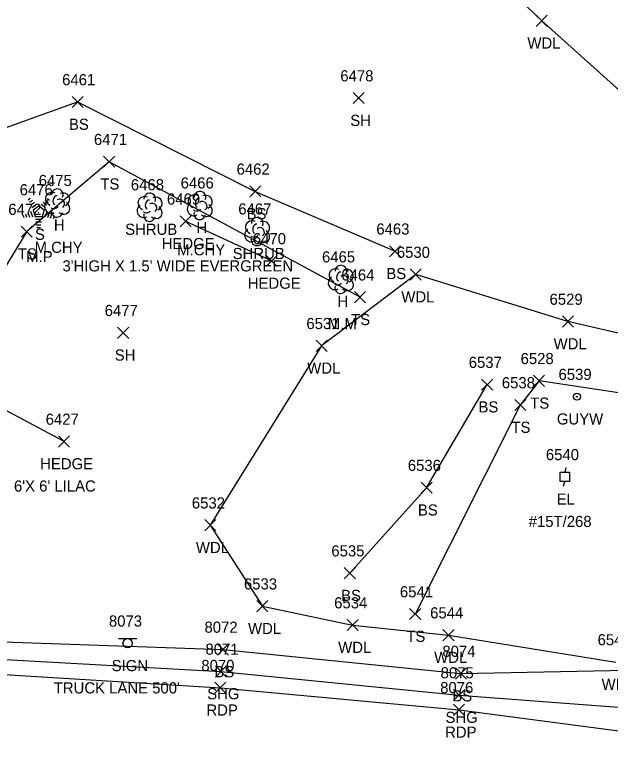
# Model space of a CAD drawing. Extents: x 1588028 to 1589597, y 137576 to 138176.
# Drawn here: x 1588667.4 to 1588774.4, y 137897.5 to 138029.2 of the extents above; entities that cross this region are included whole.
import ezdxf

# ---------------------------------------------------------------- set-up
doc = ezdxf.new("R2010")
doc.units = 0
for name, color, linetype in [('L_A', 7, 'Continuous'), ('L_C', 7, 'Continuous'), ('L_I', 7, 'Continuous'), ('L_TIC', 7, 'Continuous'), ('LAHR', 7, 'Continuous'), ('LAWA', 7, 'Continuous'), ('LELB', 7, 'Continuous'), ('LSH', 7, 'Continuous'), ('LTC', 7, 'Continuous'), ('LTD', 7, 'Continuous'), ('P_A', 7, 'Continuous'), ('P_I', 7, 'Continuous'), ('P_TIC', 7, 'Continuous'), ('PET', 7, 'Continuous'), ('PSU', 7, 'Continuous'), ('S_A', 7, 'Continuous'), ('S_C', 7, 'Continuous'), ('S_I', 7, 'Continuous'), ('SSGN', 7, 'Continuous'), ('U_A', 7, 'Continuous'), ('U_C', 7, 'Continuous'), ('U_I', 7, 'Continuous'), ('UEPT', 7, 'Continuous'), ('UPGW', 7, 'Continuous')]:
    doc.layers.add(name, color=color, linetype=linetype)

msp = doc.modelspace()

# ---------------------------------------------------------------- linework, layer by layer
at = {"layer": 'L_TIC'}
for points in [[(1588761.05, 138027.09), (1588763.05, 138029.09)], [(1588763.05, 138027.09), (1588761.05, 138029.09)], [(1588728.17, 138013.21), (1588730.17, 138015.21)], [(1588730.17, 138013.21), (1588728.17, 138015.21)], [(1588677.67, 138012.51), (1588679.67, 138014.51)], [(1588679.67, 138012.51), (1588677.67, 138014.51)], [(1588683.34, 138001.79), (1588685.34, 138003.79)], [(1588685.34, 138001.79), (1588683.34, 138003.79)], [(1588709.59, 137996.46), (1588711.59, 137998.46)], [(1588711.59, 137996.46), (1588709.59, 137998.46)], [(1588697.07, 137991.09), (1588699.07, 137993.09)], [(1588699.07, 137991.09), (1588697.07, 137993.09)], [(1588668.52, 137989.24), (1588670.52, 137991.24)], [(1588670.52, 137989.24), (1588668.52, 137991.24)], [(1588734.69, 137985.71), (1588736.69, 137987.71)], [(1588736.69, 137985.71), (1588734.69, 137987.71)], [(1588712.54, 137983.98), (1588714.54, 137985.98)], [(1588714.54, 137983.98), (1588712.54, 137985.98)], [(1588738.41, 137981.53), (1588740.41, 137983.53)], [(1588740.41, 137981.53), (1588738.41, 137983.53)], [(1588728.4, 137977.46), (1588730.4, 137979.46)], [(1588730.4, 137977.46), (1588728.4, 137979.46)], [(1588765.76, 137973.1), (1588767.76, 137975.1)], [(1588767.76, 137973.1), (1588765.76, 137975.1)], [(1588685.84, 137971.08), (1588687.84, 137973.08)], [(1588687.84, 137971.08), (1588685.84, 137973.08)], [(1588721.5, 137968.74), (1588723.5, 137970.74)], [(1588723.5, 137968.74), (1588721.5, 137970.74)], [(1588751.24, 137961.77), (1588753.24, 137963.77)], [(1588753.24, 137961.77), (1588751.24, 137963.77)], [(1588760.56, 137962.45), (1588762.56, 137964.45)], [(1588762.56, 137962.45), (1588760.56, 137964.45)], [(1588757.19, 137958.11), (1588759.19, 137960.11)], [(1588759.19, 137958.11), (1588757.19, 137960.11)], [(1588675.23, 137951.57), (1588677.23, 137953.57)], [(1588677.23, 137951.57), (1588675.23, 137953.57)], [(1588740.36, 137943.27), (1588742.36, 137945.27)], [(1588742.36, 137943.27), (1588740.36, 137945.27)], [(1588701.5, 137936.53), (1588703.5, 137938.53)], [(1588703.5, 137936.53), (1588701.5, 137938.53)], [(1588726.56, 137927.93), (1588728.56, 137929.93)], [(1588728.56, 137927.93), (1588726.56, 137929.93)], [(1588710.86, 137921.99), (1588712.86, 137923.99)], [(1588712.86, 137921.99), (1588710.86, 137923.99)], [(1588738.31, 137920.58), (1588740.31, 137922.58)], [(1588740.31, 137920.58), (1588738.31, 137922.58)], [(1588727.07, 137918.6), (1588729.07, 137920.6)], [(1588729.07, 137918.6), (1588727.07, 137920.6)], [(1588744.3, 137916.8), (1588746.3, 137918.8)], [(1588746.3, 137916.8), (1588744.3, 137918.8)], [(1588703.8, 137914.23), (1588705.8, 137916.23)], [(1588705.8, 137914.23), (1588703.8, 137916.23)], [(1588746.54, 137909.9), (1588748.54, 137911.9)], [(1588748.54, 137909.9), (1588746.54, 137911.9)]]:
    msp.add_lwpolyline(points, dxfattribs=at)
at = {"layer": 'LAHR'}
for points in [[(1588698.07, 137992.09), (1588713.54, 137984.98)], [(1588676.23, 137952.57), (1588652.59, 137965.15)]]:
    msp.add_lwpolyline(points, dxfattribs=at)
at = {"layer": 'LAWA'}
for points in [[(1588438.89, 138034.8), (1588460.15, 138038.23), (1588480.55, 138035.11), (1588505.29, 138026.54), (1588523.98, 138028.49), (1588536.66, 138053.55), (1588553.84, 138097.83), (1588585.17, 138100.47), (1588614.56, 138103.49), (1588645.11, 138105.26), (1588662.06, 138103.96), (1588684.62, 138095.19), (1588717.93, 138069.71), (1588741.65, 138047.62), (1588762.05, 138028.09), (1588788.28, 138004.54)], [(1588793.35, 137967.95), (1588766.76, 137974.1), (1588739.41, 137982.53), (1588722.5, 137969.74), (1588702.5, 137937.53), (1588711.86, 137922.99), (1588728.07, 137919.6), (1588745.3, 137917.8), (1588775.38, 137912.97)]]:
    msp.add_lwpolyline(points, dxfattribs=at)
at = {"layer": 'LELB'}
for points in [[(1588591.54, 138046.29), (1588626.32, 138039.75), (1588630.34, 138007.04), (1588626.86, 137991.11), (1588639.77, 137986.11), (1588660.41, 138007.02), (1588678.67, 138013.51), (1588710.59, 137997.46), (1588735.69, 137986.71)], [(1588729.4, 137978.46), (1588684.34, 138002.79), (1588669.52, 137990.24), (1588656.54, 137969.04)], [(1588806.13, 137923.03), (1588809.17, 137939.49), (1588786.18, 137959.73), (1588761.56, 137963.45), (1588758.19, 137959.11), (1588739.31, 137921.58)], [(1588727.56, 137928.93), (1588741.36, 137944.27), (1588752.24, 137962.77)], [(1588551.14, 137930.49), (1588555.16, 137922.7), (1588594.96, 137920.46), (1588624.61, 137918.77), (1588663.54, 137916.63), (1588704.8, 137915.23), (1588747.54, 137910.9), (1588783.34, 137911.62)]]:
    msp.add_lwpolyline(points, dxfattribs=at)
at = {"layer": 'LSH'}
for p, q in [((1588691.58, 137994.66), (1588691.58, 137994.66)), ((1588691.58, 137994.66), (1588691.58, 137994.66)), ((1588710.89, 137990.31), (1588710.89, 137990.31)), ((1588710.89, 137990.31), (1588710.89, 137990.31))]:
    msp.add_line(p, q, dxfattribs=at)
for centre in [(1588691.63, 137996.09), (1588710.93, 137991.74)]:
    msp.add_arc(centre, 1.05, 335.5272, 180.9563, dxfattribs=at)
for centre, major_axis, ratio, start_param, end_param in [((1588690.79, 137995.32), (1.21, -0.51), 0.895232, 1.570796, 4.712389), ((1588692.62, 137995.24), (-1.14, -0.48), 0.949671, 1.570796, 4.712389), ((1588690.5, 137993.95), (0.58, -1.04), 0.959034, 3.141593, 6.283185), ((1588691.37, 137995.11), (-0.208, -0.792), 0.645439, 3.141593, 6.283185), ((1588692.08, 137994.49), (-0.5, 0.667), 0.989748, 3.141593, 6.283185), ((1588691.12, 137993.91), (-0.625, -0.083), 0.423636, 0, 3.141593), ((1588692.58, 137993.82), (-1.09, 0.79), 0.841452, 1.570796, 4.712389), ((1588691.58, 137993.16), (0.26, 1.06), 0.942809, 1.570796, 4.712389), ((1588710.1, 137990.98), (1.21, -0.51), 0.895232, 1.570796, 4.712389), ((1588711.93, 137990.89), (-1.14, -0.48), 0.949671, 1.570796, 4.712389), ((1588710.68, 137990.77), (-0.208, -0.792), 0.645439, 3.141593, 6.283185), ((1588711.39, 137990.14), (-0.5, 0.667), 0.989748, 3.141593, 6.283185), ((1588709.8, 137989.6), (0.58, -1.04), 0.959034, 3.141593, 6.283185), ((1588710.43, 137989.56), (-0.625, -0.083), 0.423636, 0, 3.141593), ((1588711.89, 137989.48), (-1.09, 0.79), 0.841452, 1.570796, 4.712389), ((1588710.89, 137988.81), (0.26, 1.06), 0.942809, 1.570796, 4.712389)]:
    msp.add_ellipse(centre, major_axis=major_axis, ratio=ratio, start_param=start_param, end_param=end_param, dxfattribs=at)
at = {"layer": 'LTC'}
for p, q in [((1588669.81, 137995.97), (1588670.17, 137996.23)), ((1588673.21, 137996.21), (1588673.63, 137995.9)), ((1588670.02, 137995.5), (1588670.55, 137995.89)), ((1588670.23, 137995.04), (1588670.93, 137995.55)), ((1588670.44, 137994.57), (1588671.32, 137995.21)), ((1588670.66, 137994.12), (1588671.68, 137994.85)), ((1588671.68, 137994.85), (1588672.67, 137994.13)), ((1588672.1, 137995.16), (1588672.91, 137994.57)), ((1588672.47, 137995.51), (1588673.15, 137995.02)), ((1588672.84, 137995.86), (1588673.39, 137995.46)), ((1588669.3, 137993.46), (1588669.51, 137992.81)), ((1588669.75, 137993.68), (1588670.03, 137992.84)), ((1588670.21, 137993.9), (1588670.54, 137992.88)), ((1588670.66, 137994.12), (1588671.05, 137992.92)), ((1588672.67, 137994.13), (1588672.28, 137992.92)), ((1588673.11, 137993.85), (1588672.77, 137992.81)), ((1588673.55, 137993.6), (1588673.27, 137992.72)), ((1588668.84, 137993.25), (1588669, 137992.78)), ((1588672.28, 137992.92), (1588671.05, 137992.92)), ((1588672.24, 137992.42), (1588671.1, 137992.42)), ((1588674, 137993.35), (1588673.76, 137992.62)), ((1588674.44, 137993.1), (1588674.26, 137992.53)), ((1588672.16, 137991.92), (1588671.17, 137991.92)), ((1588672.08, 137991.42), (1588671.24, 137991.42)), ((1588671.99, 137990.92), (1588671.32, 137990.92))]:
    msp.add_line(p, q, dxfattribs=at)
at = {"layer": 'LTD'}
for p, q in [((1588674.98, 137995.42), (1588674.98, 137995.42)), ((1588674.98, 137995.42), (1588674.98, 137995.42)), ((1588700.59, 137994.98), (1588700.59, 137994.98)), ((1588700.59, 137994.98), (1588700.59, 137994.98)), ((1588725.93, 137981.71), (1588725.93, 137981.71)), ((1588725.93, 137981.71), (1588725.93, 137981.71))]:
    msp.add_line(p, q, dxfattribs=at)
for centre in [(1588675.02, 137996.85), (1588700.64, 137996.41), (1588725.97, 137983.14)]:
    msp.add_arc(centre, 1.05, 335.5272, 180.9563, dxfattribs=at)
for centre, major_axis, ratio, start_param, end_param in [((1588674.18, 137996.08), (1.21, -0.51), 0.895232, 1.570796, 4.712389), ((1588674.77, 137995.88), (-0.208, -0.792), 0.645439, 3.141593, 6.283185), ((1588675.48, 137995.25), (-0.5, 0.667), 0.989748, 3.141593, 6.283185), ((1588676.02, 137996), (-1.14, -0.48), 0.949671, 1.570796, 4.712389), ((1588699.8, 137995.65), (1.21, -0.51), 0.895232, 1.570796, 4.712389), ((1588700.38, 137995.44), (-0.208, -0.792), 0.645439, 3.141593, 6.283185), ((1588701.63, 137995.56), (-1.14, -0.48), 0.949671, 1.570796, 4.712389), ((1588673.89, 137994.71), (0.58, -1.04), 0.959034, 3.141593, 6.283185), ((1588675.98, 137994.58), (-1.09, 0.79), 0.841452, 1.570796, 4.712389), ((1588699.51, 137994.27), (0.58, -1.04), 0.959034, 3.141593, 6.283185), ((1588701.09, 137994.81), (-0.5, 0.667), 0.989748, 3.141593, 6.283185), ((1588701.59, 137994.15), (-1.09, 0.79), 0.841452, 1.570796, 4.712389), ((1588674.98, 137993.92), (0.26, 1.06), 0.942809, 1.570796, 4.712389), ((1588674.52, 137994.67), (-0.625, -0.083), 0.423636, 0, 3.141593), ((1588700.59, 137993.48), (0.26, 1.06), 0.942809, 1.570796, 4.712389), ((1588700.13, 137994.23), (-0.625, -0.083), 0.423636, 0, 3.141593), ((1588725.13, 137982.37), (1.21, -0.51), 0.895232, 1.570796, 4.712389), ((1588725.72, 137982.17), (-0.208, -0.792), 0.645439, 3.141593, 6.283185), ((1588726.97, 137982.29), (-1.14, -0.48), 0.949671, 1.570796, 4.712389), ((1588724.84, 137981), (0.58, -1.04), 0.959034, 3.141593, 6.283185), ((1588726.43, 137981.54), (-0.5, 0.667), 0.989748, 3.141593, 6.283185), ((1588726.93, 137980.87), (-1.09, 0.79), 0.841452, 1.570796, 4.712389), ((1588725.93, 137980.21), (0.26, 1.06), 0.942809, 1.570796, 4.712389), ((1588725.47, 137980.96), (-0.625, -0.083), 0.423636, 0, 3.141593)]:
    msp.add_ellipse(centre, major_axis=major_axis, ratio=ratio, start_param=start_param, end_param=end_param, dxfattribs=at)
at = {"layer": 'P_TIC'}
for points in [[(1588703.41, 137910.28), (1588705.41, 137912.28)], [(1588705.41, 137910.28), (1588703.41, 137912.28)], [(1588703.32, 137907.35), (1588705.32, 137909.35)], [(1588705.32, 137907.35), (1588703.32, 137909.35)], [(1588746.22, 137906.04), (1588748.22, 137908.04)], [(1588748.22, 137906.04), (1588746.22, 137908.04)], [(1588746.19, 137903.38), (1588748.19, 137905.38)], [(1588748.19, 137903.38), (1588746.19, 137905.38)]]:
    msp.add_lwpolyline(points, dxfattribs=at)
at = {"layer": 'PET'}
msp.add_lwpolyline([(1588422.16, 137923.17), (1588469.2, 137920.73), (1588503.28, 137919.24), (1588517.55, 137918.56), (1588549.94, 137917.25), (1588592.35, 137915.11), (1588643.26, 137911.75), (1588663.5, 137910.85), (1588704.32, 137908.35), (1588747.19, 137904.38), (1588787.69, 137899.08), (1588825.32, 137893.63), (1588865.15, 137887.82), (1588905.82, 137880.77), (1588917.24, 137863.85), (1588927.99, 137847.51)], dxfattribs=at)
at = {"layer": 'PSU'}
msp.add_lwpolyline([(1588548.35, 137920.32), (1588592.38, 137917.18), (1588643.62, 137914.8), (1588663.46, 137913.57), (1588704.41, 137911.28), (1588747.22, 137907.04), (1588788.55, 137903.91), (1588803.43, 137901.36)], dxfattribs=at)
at = {"layer": 'SSGN'}
for p, q in [((1588686, 137917.19), (1588689.33, 137917.19)), ((1588687.65, 137916.35), (1588687.65, 137916.35))]:
    msp.add_line(p, q, dxfattribs=at)
msp.add_circle((1588687.65, 137916.35), 0.833, dxfattribs=at)
at = {"layer": 'UEPT'}
for p, q in [((1588766.35, 137947.87), (1588766.19, 137947.04)), ((1588765.35, 137945.37), (1588765.35, 137947.04)), ((1588765.35, 137947.04), (1588767.02, 137947.04)), ((1588766.19, 137946.21), (1588766.19, 137946.21)), ((1588767.02, 137947.04), (1588767.02, 137945.37)), ((1588767.02, 137945.37), (1588765.35, 137945.37)), ((1588765.94, 137944.54), (1588766.19, 137945.37))]:
    msp.add_line(p, q, dxfattribs=at)
at = {"layer": 'UPGW'}
for radius in [0.625, 0.0833]:
    msp.add_circle((1588768.38, 137960.61), radius, dxfattribs=at)

# ---------------------------------------------------------------- texts
at = {"layer": 'L_A'}
for s, p in [('WDL', (1588759.47, 138023.09)), ('SH', (1588727.65, 138009.21)), ('BS', (1588677.11, 138008.51)), ('TS', (1588682.75, 137997.79)), ('BS', (1588709.03, 137992.46)), ('H', (1588674.41, 137990.42)), ('SHRUB', (1588687.21, 137989.66)), ('H', (1588700.03, 137989.98)), ('S', (1588671, 137988.76)), ('HEDGE', (1588693.77, 137987.09)), ('TS', (1588667.93, 137985.24)), ('SHRUB', (1588706.52, 137985.31)), ('BS', (1588734.13, 137981.71)), ('HEDGE', (1588709.24, 137979.98)), ('WDL', (1588736.82, 137977.53)), ('H', (1588725.36, 137976.71)), ('TS', (1588727.8, 137973.46)), ('WDL', (1588764.18, 137969.1)), ('SH', (1588685.33, 137967.08)), ('WDL', (1588719.92, 137964.74)), ('BS', (1588750.68, 137957.77)), ('TS', (1588759.97, 137958.45)), ('TS', (1588756.6, 137954.11)), ('HEDGE', (1588671.94, 137947.57)), ('BS', (1588739.8, 137939.27)), ('WDL', (1588699.91, 137932.53)), ('BS', (1588726, 137923.93)), ('WDL', (1588709.28, 137917.99)), ('TS', (1588737.72, 137916.58)), ('WDL', (1588725.48, 137914.6)), ('WDL', (1588742.72, 137912.8)), ('BS', (1588703.24, 137910.23)), ('WDL', (1588772.8, 137907.97)), ('BS', (1588745.98, 137905.9))]:
    msp.add_text(s, height=2, dxfattribs=at).set_placement(p)
at = {"layer": 'L_C'}
for s, p in [('M.CHY', (1588670.94, 137986.42)), ('M.CHY', (1588696.56, 137985.98)), ('M.P', (1588669.43, 137984.76)), ("3'HIGH X 1.5' WIDE EVERGREEN", (1588675.94, 137983.09)), ('M.M', (1588723.63, 137972.71)), ("6'X 6' LILAC", (1588667.23, 137943.57))]:
    msp.add_text(s, height=2, dxfattribs=at).set_placement(p)
at = {"layer": 'L_I'}
for s, p in [('6461', (1588675.88, 138016.51)), ('6478', (1588725.86, 138017.21)), ('6471', (1588681.6, 138005.79)), ('6462', (1588707.23, 138000.46)), ('6475', (1588671.67, 137998.42)), ('6476', (1588668.25, 137996.76)), ('6468', (1588688.23, 137997.66)), ('6466', (1588697.18, 137997.98)), ('6469', (1588694.71, 137995.09)), ('6472', (1588666.21, 137993.24)), ('6467', (1588707.53, 137993.31)), ('6463', (1588732.33, 137989.71)), ('6470', (1588710.15, 137987.98)), ('6530', (1588736.01, 137985.53)), ('6465', (1588722.57, 137984.71)), ('6464', (1588726.04, 137981.46)), ('6529', (1588763.45, 137977.1)), ('6477', (1588683.53, 137975.08)), ('6531', (1588719.76, 137972.74)), ('6528', (1588758.25, 137966.45)), ('6537', (1588748.93, 137965.77)), ('6538', (1588754.88, 137962.11)), ('6427', (1588672.93, 137955.57)), ('6536', (1588737.99, 137947.27)), ('6532', (1588699.19, 137940.53)), ('6535', (1588724.25, 137931.93)), ('6533', (1588708.55, 137925.99)), ('6541', (1588736.57, 137924.58)), ('6534', (1588724.76, 137922.6)), ('6544', (1588742, 137920.8)), ('8072', (1588701.46, 137918.23)), ('6545', (1588772.08, 137915.97)), ('8074', (1588744.2, 137913.9))]:
    msp.add_text(s, height=2, dxfattribs=at).set_placement(p)
at = {"layer": 'LTC'}
msp.add_text('.', height=1.04, rotation=270, dxfattribs=at).set_placement((1588671.56, 137993.86))
at = {"layer": 'P_A'}
for s, p in [('SHG', (1588701.95, 137906.28)), ('RDP', (1588701.81, 137903.35)), ('SHG', (1588744.75, 137902.04)), ('RDP', (1588744.68, 137899.38))]:
    msp.add_text(s, height=2, dxfattribs=at).set_placement(p)
at = {"layer": 'P_I'}
for s, p in [('8071', (1588701.64, 137914.28)), ('8070', (1588700.89, 137911.35)), ('8075', (1588743.88, 137910.04)), ('8076', (1588743.8, 137907.38))]:
    msp.add_text(s, height=2, dxfattribs=at).set_placement(p)
at = {"layer": 'S_A'}
msp.add_text('SIGN', height=2, dxfattribs=at).set_placement((1588684.78, 137911.33))
at = {"layer": 'S_C'}
msp.add_text("TRUCK LANE 500'", height=2, dxfattribs=at).set_placement((1588674.38, 137907.33))
at = {"layer": 'S_I'}
msp.add_text('8073', height=2, dxfattribs=at).set_placement((1588684.29, 137919.33))
at = {"layer": 'U_A'}
for s, p in [('GUYW', (1588764.77, 137955.61)), ('EL', (1588764.72, 137941.21))]:
    msp.add_text(s, height=2, dxfattribs=at).set_placement(p)
at = {"layer": 'U_C'}
msp.add_text('#15T/268', height=2, dxfattribs=at).set_placement((1588759.7, 137937.21))
at = {"layer": 'U_I'}
for s, p in [('6539', (1588765.06, 137963.61)), ('6540', (1588762.79, 137949.21))]:
    msp.add_text(s, height=2, dxfattribs=at).set_placement(p)

doc.saveas('drawing.dxf')
